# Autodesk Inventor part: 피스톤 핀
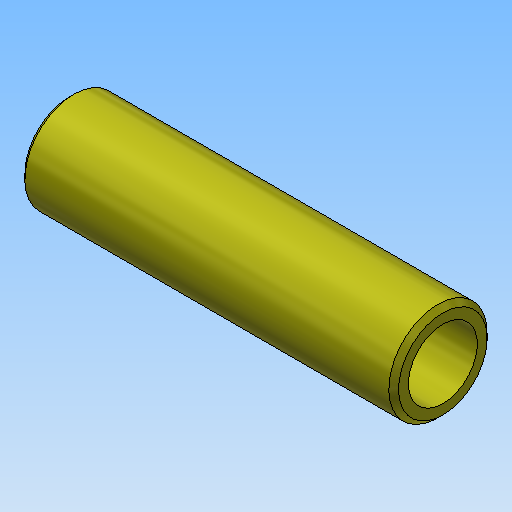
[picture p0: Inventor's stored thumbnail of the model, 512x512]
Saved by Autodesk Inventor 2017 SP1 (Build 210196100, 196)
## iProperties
Created: 2017-05
Part Number: 피스톤 핀
Material: 알루미늄 6061
Document SubType Name: Modeling
Designer: mduedu
Density: 2.71 g/cm^3
Mass: 4.10432 g
Surface Area: 20.9053 cm^2
Volume: 1.51451 cm^3
Appearance: 노란색
Author: mduedu
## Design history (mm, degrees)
sketch "스케치1"
  geometry: C1 r 5 at (0, 0); C2 r 3.5 at (0, 0); 1 further point
  constraints: 2 centre point, 2 coincident
  dimensions: "d0" = 10 diameter of C1; "d1" = 7 diameter of C2
extrude "돌출1" new body sketch "스케치1" stored distance "d2" = 38; taper "d3" = 0 deg
chamfer "모따기1" distance "d4" = 0.5; stored, may be unused: second distance "d5" = 2, angle "d6" = 45 deg
node "솔리드1"
